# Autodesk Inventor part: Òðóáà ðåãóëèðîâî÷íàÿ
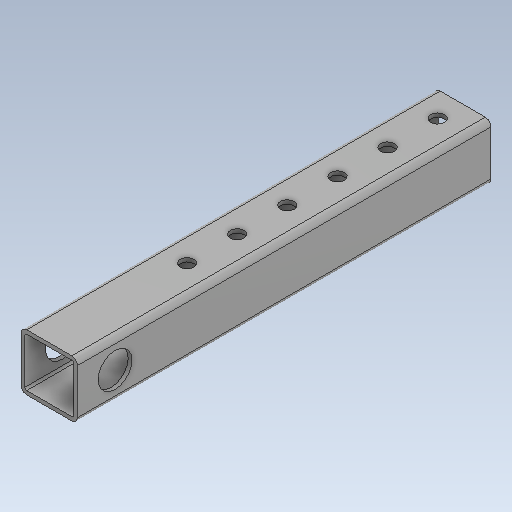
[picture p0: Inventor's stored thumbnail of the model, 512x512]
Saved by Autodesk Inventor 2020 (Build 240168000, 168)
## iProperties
Created: 1900-01
Part Number: Òðóáà ðåãóëèðîâî÷íàÿ
Material: Générique
Document SubType Name: Modeling
Designer: bruno
Density: 1 g/cm^3
Appearance: Par défaut
Author: bruno
Revision Number: ANYUNSPECIFIED
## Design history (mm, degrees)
feature "Base1"
node "Solide1"
